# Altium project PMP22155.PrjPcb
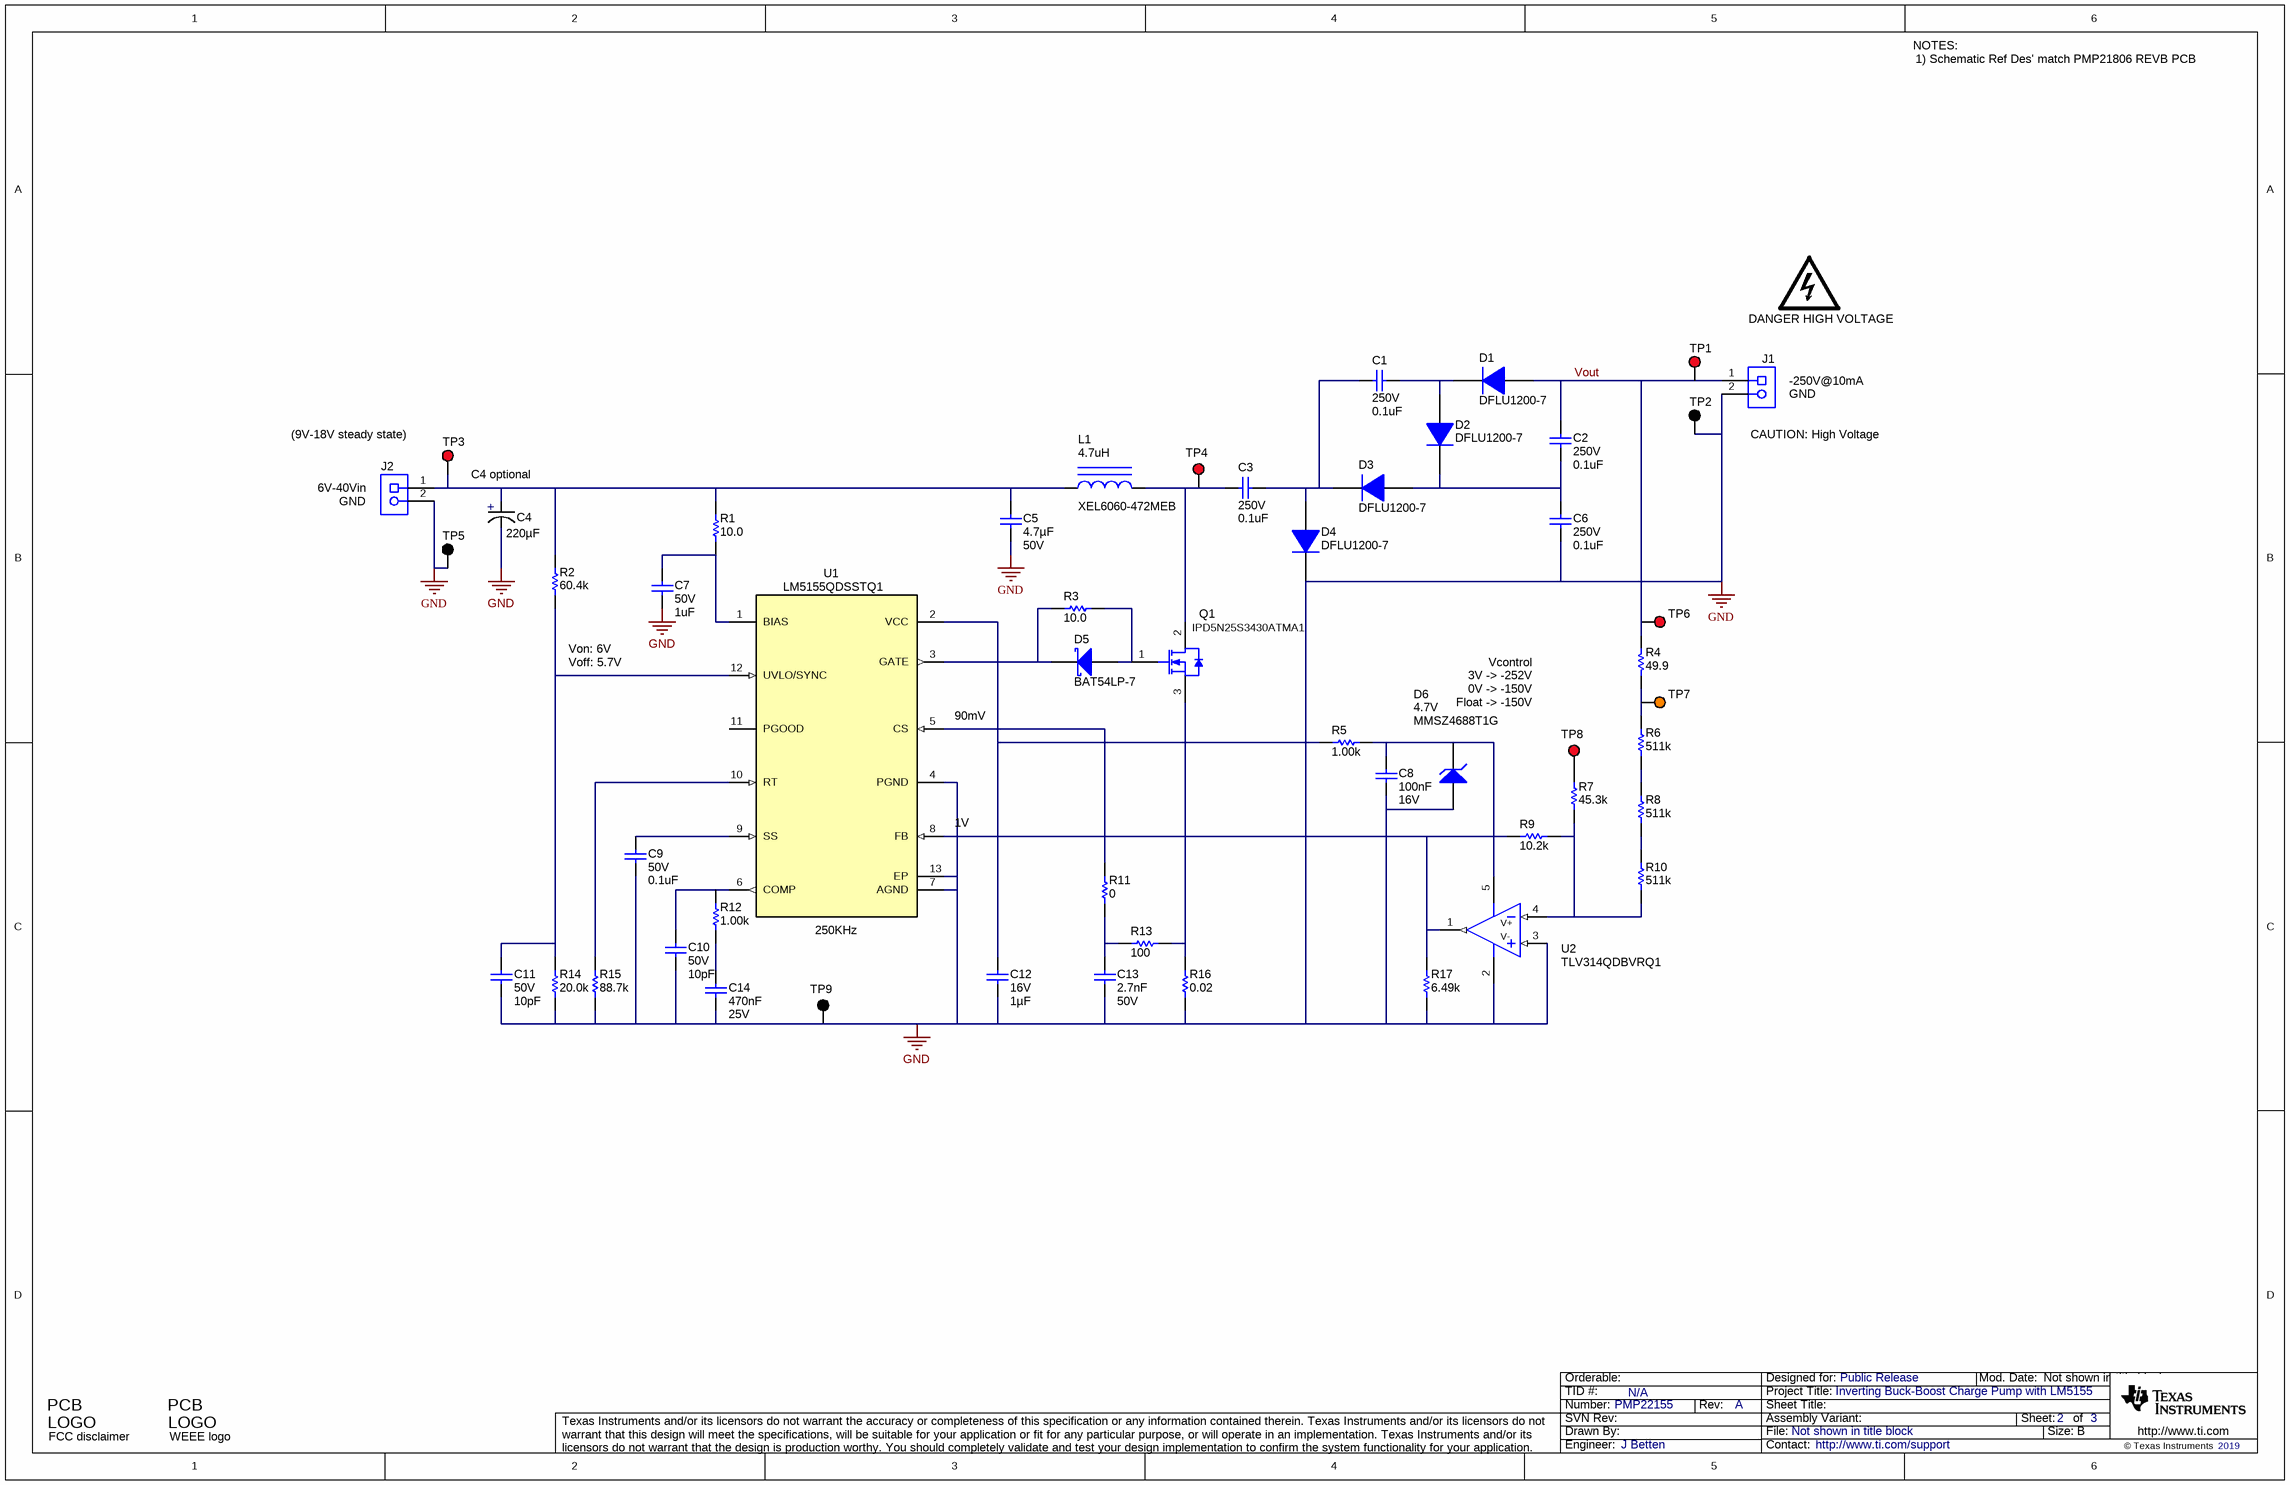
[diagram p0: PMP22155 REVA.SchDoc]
CopyrightYear: 2019; PCB_Layout: J Betten; PCB_Rev: B; PRJ_Customer: Public Release; PRJ_Engineer: J Betten; PRJ_Number: PMP22155; PRJ_Title: Inverting Buck-Boost Charge Pump with LM5155; SCH_Rev: A; TechSupport: http://www.ti.com/support; TID: N/A
1 sheet, 55 parts. Net scope: global (net labels, ports and power ports of the same name join across sheets).
Board file: PMP21806 REVB PCB.PcbDoc

## Sheet PMP22155 REVA.SchDoc
size 431 x 279 mm; Date: Not shown in title block; ApprovedBy: Not shown in title block; CheckedBy: Not shown in title block; Author: Not shown in title block; CompanyName: Not shown in title block; Engineer: Not shown in title block; Organization: Not shown in title block; Address1: Not shown in title block; Address2: Not shown in title block; Address3: Not shown in title block; Address4: Not shown in title block; DocumentNumber: 2; Revision: Use project parameter SCH_Rev; SheetNumber: 2; SheetTotal: 3; PageSetup: Record=PageOptions¦CenterHorizontal=True¦CenterVertical=True¦PrintScale=1.00¦XCorrection=1.00¦YCorrection=1.00¦PrintKind=0¦BorderSize=5000000¦LeftOffset=0¦BottomOffset=0¦Orientation=2¦PaperLength=1000¦PaperWidth=1000¦Scale=100¦PaperSource=15¦PrintQuality=600¦MediaType=1¦DitherType=10¦PaperKind=Letter¦PrintScaleMode=1

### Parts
C1  VDC_V: 250V  ValueDisplayed: 0.1uF  [1210_220]  (hidden comment: GRM32DR72E104KW01L)
C2  VDC_V: 250V  ValueDisplayed: 0.1uF  [1210_220]  (hidden comment: GRM32DR72E104KW01L)
C3  VDC_V: 250V  ValueDisplayed: 0.1uF  [1210_220]  (hidden comment: GRM32DR72E104KW01L)
C4  Cap_F: 220µF  [FP-EEHZS1H221P_RADIAL_SMD-MFG]  (hidden comment: EEHZS1H221P)
C5  ValueDisplayed: 4.7µF  VDC_V: 50V  [1206_190]  (hidden comment: CGA5L3X7R1H475K160AE)
C6  VDC_V: 250V  ValueDisplayed: 0.1uF  [1210_220]  (hidden comment: GRM32DR72E104KW01L)
C7  VDC_V: 50V  ValueDisplayed: 1uF  [0805_HV]  (hidden comment: CGA4J3X7R1H105K125AB)
C8  Cap_F: 100nF  VDC_V: 16V  [0603S]  (hidden comment: CGJ3E2X7R1C104K080AA)
C9  VDC_V: 50V  ValueDisplayed: 0.1uF  [0603L]  (hidden comment: CGA3E2X7R1H104K080AA)
C10  VDC_V: 50V  ValueDisplayed: 10pF  [0603L]  (hidden comment: GRM1885C1H100JA01D)
C11  VDC_V: 50V  ValueDisplayed: 10pF  [0603L]  (hidden comment: GRM1885C1H100JA01D)
C12  VDC_V: 16V  ValueDisplayed: 1µF  [0603L]  (hidden comment: GCM188R71C105KA64J)
C13  Cap_F: 2.7nF  VDC_V: 50V  [0603S]  (hidden comment: GRM188R71H272KA01D)
C14  Cap_F: 470nF  VDC_V: 25V  [0603]  (hidden comment: GCM188R71E474KA64D)
D1  DFLU1200-7  [PowerDI123]
D2  DFLU1200-7  [PowerDI123]
D3  DFLU1200-7  [PowerDI123]
D4  DFLU1200-7  [PowerDI123]
D5  BAT54LP-7  [X1-DFN1006-2]
D6  MMSZ4688T1G  value 4.7V  [SOD-123]
J1  ED555/2DS  [TERM_BLK_ED555-2DS]  (value not drawn)
J2  ED555/2DS  [TERM_BLK_ED555-2DS]  (value not drawn)
L1  XEL6060-472MEB  ValueDisplayed: 4.7uH  [XEL6060]
LOGO1  DANGER HIGH VOLTAGE  [IEC_HighVoltage_Small]  (no BOM)
Logo2  FCC disclaimer  [FCC_disclaimer]  (no BOM)
Logo3  WEEE logo  [WEEE_Minimum]  (no BOM)
Q1  IPD5N25S3430ATMA1  [DPAK]
R1  ValueDisplayed: 10.0  [0603L]  (hidden comment: CRCW060310R0FKEA)
R2  ValueDisplayed: 60.4k  [0603L]  (hidden comment: CRCW060360K4FKEA)
R3  ValueDisplayed: 10.0  [0603L]  (hidden comment: CRCW060310R0FKEA)
R4  value 49.9  [0603L]  (hidden comment: CRCW060349R9FKEA)
R5  ValueDisplayed: 1.00k  [0603S]  (hidden comment: CRCW06031K00FKEA)
R6  ValueDisplayed: 511k  [0603L]  (hidden comment: CRCW0603511KFKEA)
R7  ValueDisplayed: 45.3k  [0603]  (hidden comment: CRCW060345K3FKEA)
R8  ValueDisplayed: 511k  [0603L]  (hidden comment: CRCW0603511KFKEA)
R9  ValueDisplayed: 10.2k  [0603]  (hidden comment: CRCW060310K2FKEA)
R10  ValueDisplayed: 511k  [0603L]  (hidden comment: CRCW0603511KFKEA)
R11  ValueDisplayed: 0  [0603L]  (hidden comment: CRCW06030000Z0EA)
R12  ValueDisplayed: 1.00k  [0603]  (hidden comment: CRCW06031K00FKEA)
R13  ValueDisplayed: 100  [0603L]  (hidden comment: CRCW0603100RFKEA)
R14  ValueDisplayed: 20.0k  [0603L]  (hidden comment: CRCW060320K0FKEA)
R15  ValueDisplayed: 88.7k  [0603L]  (hidden comment: CRCW060388K7FKEA)
R16  ValueDisplayed: 0.02  [1206]  (hidden comment: CSR1206FK20L0)
R17  ValueDisplayed: 6.49k  [0603L]  (hidden comment: CRCW06036K49FKEA)
TP1  5010  [Keystone5010]  (value not drawn)
TP2  5011  [Keystone5011]  (value not drawn)
TP3  5010  [Keystone5010]  (value not drawn)
TP4  5000  [Keystone5000]  (value not drawn)
TP5  5011  [Keystone5011]  (value not drawn)
TP6  5010  [Keystone5010]  (value not drawn)
TP7  5013  [Keystone5013]  (value not drawn)
TP8  5000  [Keystone5000]  (value not drawn)
TP9  5001  [Keystone5001]  (value not drawn)
U1  LM5155QDSSTQ1  [DSS0012C]
U2  TLV314QDBVRQ1  [DBV0005A_N]

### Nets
GND: C4.1(CATHODE) C5.2 C6.2 C7.2 C8.2 C9.2 C10.2 C11.2 C12.1 C13.2 C14.2 D4.1(K) D6.2(A) J1.2 J2.2 R14.1 R15.1 R16.1 R17.1 TP2.1 TP5.1 TP9.1 U1.4(PGND) U1.7(AGND) U1.13(EP) U2.2(V-) U2.3(IN+)
Vout: C2.1 D1.2(A) J1.1 R4.1 TP1.1 TP6.1
NetC1_1: C1.1 C3.2 D3.1(K) D4.2(A)
NetC1_2: C1.2 D1.1(K) D2.2(A)
NetC2_2: C2.2 C6.1 D2.1(K) D3.2(A)
NetC3_1: C3.1 L1.2 Q1.2(D) TP4.1
NetC4_2: C4.2(ANODE) C5.1 J2.1 L1.1 R1.2 R2.2 TP3.1
NetC7_1: C7.1 R1.1 U1.1(BIAS)
NetC8_1: C8.1 D6.1(K) R5.1 U2.5(V+)
NetC9_1: C9.1 U1.9(SS)
NetC10_1: C10.1 R12.2 U1.6(COMP)
NetC11_1: C11.1 R2.1 R14.2 U1.12(UVLO/SYNC)
NetC12_2: C12.2 R5.2 U1.2(VCC)
NetC13_1: C13.1 R11.1 R13.1
NetC14_1: C14.1 R12.1
NetD5_1: D5.1(K) R3.2 U1.3(GATE)
NetD5_2: D5.2(A) Q1.1(G) R3.1
NetQ1_3: Q1.3(S) R13.2 R16.2
NetR4_2: R4.2 R6.2 TP7.1
NetR6_1: R6.1 R8.2
NetR7_1: R7.1 R9.2 R10.1 U2.4(IN-)
NetR7_2: R7.2 TP8.1
NetR8_1: R8.1 R10.2
NetR9_1: R9.1 R17.2 U1.8(FB) U2.1(OUT)
NetR11_2: R11.2 U1.5(CS)
NetR15_2: R15.2 U1.10(RT)

Not connected (* = marked no-connect by the designer): U1 11(PGOOD)

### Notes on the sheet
- NOTES:
- 1) Schematic Ref Des' match PMP21806 REVB PCB
- (9V-18V steady state)
- (near J1) -250V@10mA
- (near J1) GND
- (near J1) CAUTION: High Voltage
- (near J2) 6V-40Vin
- (near J2) GND
- C4 optional
- Von: 6V
- Voff: 5.7V
- Vcontrol
- 3V -> -252V
- 0V -> -150V
- Float -> -150V
- (near U1) 90mV
- 1V
- (near U1) 250KHz

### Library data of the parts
C1-C3 C6 = CMP-0009192-2: CAP, CERM, 0.1 uF, 250 V, +/- 10%, X7R, 1210; Manufacturer: MuRata; TaMin_C: -55°C; Polarized: N; SizeAreaWB_mm2: 14.7; Value1: Unknown; U/M: EA; Value: 0.1uF; TaMax_C: 125°C; SizeZ_mm: 2.2; SizeX_mm: 3.2; SizeY_mm: 2.5; Cap_Case: 1210; SizeArea_mm2: 8; Cap_F: 100nF; AEC Category: Q200
C4 = CMP-0087071-1: 220µF 50V Aluminum Polymer Capacitor Radial, Can - SMD 13 mOhm 4000 Hrs @ 125°C; Manufacturer: Panasonic Electronic Components; SizeZ_mm: 16.8mm; AEC Grade: Grade 1; Symbol Name: SYM-EEHZS1H221P; IRMS_A: 3.7A; Tolerance_%: 20%; AEC Qualified: Yes
C5 = CMP-0085349-1: CAP, CERM, 4.7 µF, 50 V,+/- 10%, X7R, AEC-Q200 Grade 1, 1206; Manufacturer: TDK; Cap_Case: 1206; AEC Category: Q200; SizeY_mm: 1.6; TaMin_C: -55°C; TaMax_C: 125°C; U/M: EA; AEC Qualified: Y; SizeAreaWB_mm2: 10.92; AEC Grade: 1; SizeZ_mm: 1.9; SizeArea_mm2: 5.12; Value: 4.7uF; Polarized: N; SizeX_mm: 3.2
C7 = CMP-0007976-2: CAP, CERM, 1 uF, 50 V, +/- 10%, X7R, AEC-Q200 Grade 1, 0805; Manufacturer: TDK; TaMin_C: -55°C; ESR_ohm: 8.782m; Polarized: N; SizeAreaWB_mm2: 6.75; Value1: 0.008782 ohm; U/M: EA; Value: 1uF; TaMax_C: 125°C; SizeZ_mm: 1.45; SizeX_mm: 2; SizeY_mm: 1.25; Cap_Case: 0805; SizeArea_mm2: 2.5; AEC Qualified: Y; Cap_F: 1µF; IRMS_A: 2.20488A; AEC Grade: 1; AEC Category: Q200
C8 = CMP-0007106-4: CAP, CERM, 0.1 uF, 16 V, +/- 10%, X7R, AEC-Q200 Grade 1, 0603; Manufacturer: TDK; TaMin_C: -55°C; Polarized: N; SizeAreaWB_mm2: 4.68; Value1: Unknown; U/M: EA; Value: 0.1uF; TaMax_C: 125°C; SizeZ_mm: 1; SizeX_mm: 1.6; SizeY_mm: 0.8; Cap_Case: 0603; SizeArea_mm2: 1.28; AEC Qualified: Y; AEC Category: Q200
C9 = CMP-0007078-4: CAP, CERM, 0.1 uF, 50 V, +/- 10%, X7R, AEC-Q200 Grade 1, 0603; Manufacturer: TDK; TaMin_C: -55°C; ESR_ohm: 0.0296; Polarized: N; SizeAreaWB_mm2: 4.68; Value1: 0.0296 ohm; U/M: EA; Value: 0.1uF; TaMax_C: 125°C; SizeZ_mm: 1; SizeX_mm: 1.6; SizeY_mm: 0.8; Cap_Case: 0603; SizeArea_mm2: 1.28; AEC Qualified: Y; Cap_F: 100nF; IRMS_A: 9.7199dA; AEC Category: Q200
C10 C11 = CMP-0007170-4: CAP, CERM, 10 pF, 50 V, +/- 5%, C0G/NP0, 0603; Manufacturer: MuRata; TaMin_C: -55°C; Polarized: N; SizeAreaWB_mm2: 4.68; Value1: Unknown; U/M: EA; Value: 10pF; TaMax_C: 125°C; SizeZ_mm: 1; SizeX_mm: 1.6; SizeY_mm: 0.8; Cap_Case: 0603; SizeArea_mm2: 1.28; AEC Category: Q200
C12 = CMP-0079154-1: CAP, CERM, 1 µF, 16 V,+/- 10%, X7R, AEC-Q200 Grade 1, 0603; Manufacturer: MuRata; SizeAreaWB_mm2: 4.68; SizeArea_mm2: 1.28; AEC Qualified: Y; AEC Category: Q200; Value: 1uF; TaMax_C: 125°C; SizeZ_mm: 1; Polarized: N; TaMin_C: -55°C; SizeY_mm: 0.8; U/M: EA; SizeX_mm: 1.6; Cap_Case: 0603
C13 = CMP-0007447-4: CAP, CERM, 2700 pF, 50 V, +/- 10%, X7R, 0603; Manufacturer: MuRata; TaMin_C: -55°C; Polarized: N; SizeAreaWB_mm2: 4.68; Value1: Unknown; U/M: EA; Value: 2700pF; TaMax_C: 125°C; SizeZ_mm: 1; SizeX_mm: 1.6; SizeY_mm: 0.8; Cap_Case: 0603; SizeArea_mm2: 1.28; AEC Category: Q200
C14 = CMP-0007142-4: CAP, CERM, 0.47 uF, 25 V, +/- 10%, X7R, AEC-Q200 Grade 1, 0603; Manufacturer: MuRata; TaMin_C: -55°C; Polarized: N; SizeAreaWB_mm2: 4.68; Value1: Unknown; U/M: EA; Value: 0.47uF; TaMax_C: 125°C; SizeZ_mm: 1; SizeX_mm: 1.6; SizeY_mm: 0.8; SizeArea_mm2: 1.28; AEC Qualified: Y; AEC Category: Q200
D1-D4 = CMP-0077072-2: Diode, Superfast Rectifier, 200 V, 1 A, AEC-Q101, PowerDI123; Manufacturer: Diodes Inc.; Vf_V: 980mV; Value: 200V; Value1: 1A; Value2: 0.98V; TJmax_C: 150°C; AEC Category: Q101; AEC Qualified: Y; Green_Lifecycle: Not Set; Green_REACh: Incomplete; SizeArea_mm2: 6.586; SizeAreaWB_mm2: 13.066; SizeX_mm: 3.7; SizeY_mm: 1.78; SizeZ_mm: 0.98
D5 = CMP-0076931-2: Diode, Schottky, 30 V, 0.2 A, 1.00x0.50x0.60mm; Manufacturer: Diodes Inc.; Vr_V: 30V; SizeX_mm: 1.0; SizeZ_mm: 0.53; Io_A: 200mA; Value: 30V; Vf_V: 1V; AEC Category: Q101; Green_Lifecycle: Not Set; SizeAreaWB_mm2: 3.2; Value1: 0.2A; Green_REACh: Incomplete; SizeY_mm: 0.6
D6 = CMP-0005785-3: Diode, Zener, 4.7 V, 500 mW, SOD-123; Manufacturer: ON Semiconductor; Value1: 0.5W; RJA_CperW: 340; SizeAreaWB_mm2: 13.095; Power_W: 500mW; SizeX_mm: 3.85; SizeY_mm: 1.7; SizeZ_mm: 1.35; SizeArea_mm2: 6.545; AEC Category: Q101
J1 J2 = CMP-0074913-1: Terminal Block, 3.5mm Pitch, 2x1, TH; Manufacturer: On-Shore Technology; Cert_CULUS: Y; CNHeader: False; ContactFinish: Brass; CT: True; Current_A: 6A; Gender: Female; Green_Lifecycle: Active; Green_REACh: Passed; Pitch_mm: 3.5; Row_Count: 1; Shrouded: N; Voltage_V: 150V
L1 = CMP-0061110-1: Inductor, Shielded, Composite, 4.7 uH, 11.4 A, 0.01502 ohm, AEC-Q200 Grade 1, SMD; Manufacturer: Coilcraft; Isat: 11.4A @ 30% inductance drop; Irms: 12.1A @ 40C rise; SizeAreaWB_mm2: 71.5616; Value: 4.7uH; Imax_A: 11.4A; SizeZ_mm: 6.1; SizeX_mm: 6.36; SizeY_mm: 6.56; SizeArea_mm2: 41.7216; Ind_H: 4.7µH; AEC Qualified: Y; AEC Grade: 1; AEC Category: Q200
LOGO1 = CMP-0074835-1: IEC 61010-1 High Voltage Warning; SymbolCreator: a0412235
Logo2 = CMP-0074847-1: FCC_disclaimer; Library Reference: Logo
Logo3 = CMP-0074769-1
Q1 = CMP-0082696-2: MOSFET, N-CH, 250 V, 5 A, AEC-Q101, DPAK; Manufacturer: Infineon Technologies; Alternate Manufacturer: None; Value2: 4.7 nC; AEC Qualified: Y; SizeX_mm: 9.91; VdsMax_V: 250V; ChType: N; Value: 250V; AEC Category: Q101; SizeY_mm: 6.54; SizeZ_mm: 2.29; Value1: ? ohm; SizeArea_mm2: 64.8114; ChMode: Enhancement; Vgs_V: 20V; QgTyp_nC: 4.7; IdsMax_A: 5A; SizeAreaWB_mm2: 101.7114
R1 R3 = CMP-0022003-4: RES, 10.0, 1%, 0.1 W, AEC-Q200 Grade 0, 0603; Manufacturer: Vishay-Dale; Power_W: 100mW; TempCo: 100 ppm/C; Value_Code: 10R0; Value: 10.0; EIA_Code: E96; Res_ohm: 10; SizeX_mm: 1.6; SizeY_mm: 0.8; SizeZ_mm: 1; Value2: 0.1W; SizeArea_mm2: 1.28; AEC Qualified: Y; VDC_V: 75V; AEC Category: Q200; AEC Grade: 0
R2 = CMP-0022532-4: RES, 60.4 k, 1%, 0.1 W, AEC-Q200 Grade 0, 0603; Manufacturer: Vishay-Dale; Power_W: 100mW; TempCo: 100 ppm/C; Value_Code: 60k4; Value: 60.4k; EIA_Code: E96; SizeX_mm: 1.6; SizeY_mm: 0.8; SizeZ_mm: 1; Value2: 0.1W; SizeArea_mm2: 1.28; AEC Qualified: Y; VDC_V: 75V; AEC Category: Q200; AEC Grade: 0
R4 = CMP-0022448-4: RES, 49.9, 1%, 0.1 W, AEC-Q200 Grade 0, 0603; Manufacturer: Vishay-Dale; Value_Code: 49R9; Power_W: 100mW; Value2: 0.1W; VDC_V: 75V; TempCo: 100 ppm/C; EIA_Code: E96; AEC Category: Q200; AEC Grade: 0; AEC Qualified: Y; SizeArea_mm2: 1.28; SizeX_mm: 1.6; SizeY_mm: 0.8; SizeZ_mm: 1
R5 R12 = CMP-0022109-5: RES, 1.00 k, 1%, 0.1 W, AEC-Q200 Grade 0, 0603; Manufacturer: Vishay-Dale; Power_W: 100mW; TempCo: 100 ppm/C; Value_Code: 1k00; Value: 1.00k; EIA_Code: E96; Res_ohm: 1k; SizeX_mm: 1.6; SizeY_mm: 0.8; SizeZ_mm: 1; Value2: 0.1W; SizeArea_mm2: 1.28; AEC Qualified: Y; VDC_V: 75V; AEC Category: Q200; AEC Grade: 0
R6 R8 R10 = CMP-0022480-4: RES, 511 k, 1%, 0.1 W, AEC-Q200 Grade 0, 0603; Manufacturer: Vishay-Dale; Power_W: 100mW; TempCo: 100 ppm/C; Value: 511k; EIA_Code: E96; SizeX_mm: 1.6; SizeY_mm: 0.8; SizeZ_mm: 1; Value2: 0.1W; SizeArea_mm2: 1.28; AEC Qualified: Y; VDC_V: 75V; AEC Category: Q200; AEC Grade: 0
R7 = CMP-0022430-4: RES, 45.3 k, 1%, 0.1 W, AEC-Q200 Grade 0, 0603; Manufacturer: Vishay-Dale; Power_W: 100mW; TempCo: 100 ppm/C; Value_Code: 45k3; Value: 45.3k; EIA_Code: E96; SizeX_mm: 1.6; SizeY_mm: 0.8; SizeZ_mm: 1; Value2: 0.1W; SizeArea_mm2: 1.28; AEC Qualified: Y; VDC_V: 75V; AEC Category: Q200; AEC Grade: 0
R9 = CMP-0021999-4: RES, 10.2 k, 1%, 0.1 W, AEC-Q200 Grade 0, 0603; Manufacturer: Vishay-Dale; Power_W: 100mW; TempCo: 100 ppm/C; Value_Code: 10k2; Value: 10.2k; EIA_Code: E96; SizeX_mm: 1.6; SizeY_mm: 0.8; SizeZ_mm: 1; Value2: 0.1W; SizeArea_mm2: 1.28; AEC Qualified: Y; VDC_V: 75V; AEC Category: Q200; AEC Grade: 0
R11 = CMP-0025697-4: RES, 0, 5%, 0.1 W, AEC-Q200 Grade 0, 0603; Manufacturer: Vishay-Dale; Power_W: 100mW; TempCo: 200 ppm/C; Value_Code: 0000; Value: 0; EIA_Code: E24; SizeX_mm: 1.6; SizeY_mm: 0.8; SizeZ_mm: 1; Value2: 0.1W; SizeArea_mm2: 1.28; AEC Qualified: Y; VDC_V: 75V; AEC Category: Q200
R13 = CMP-0021991-4: RES, 100, 1%, 0.1 W, AEC-Q200 Grade 0, 0603; Manufacturer: Vishay-Dale; Power_W: 100mW; TempCo: 100 ppm/C; Value_Code: 100R; Value: 100; EIA_Code: E96; SizeX_mm: 1.6; SizeY_mm: 0.8; SizeZ_mm: 1; Value2: 0.1W; SizeArea_mm2: 1.28; AEC Qualified: Y; VDC_V: 75V; AEC Category: Q200; AEC Grade: 0
R14 = CMP-0022204-4: RES, 20.0 k, 1%, 0.1 W, AEC-Q200 Grade 0, 0603; Manufacturer: Vishay-Dale; Power_W: 100mW; TempCo: 100 ppm/C; Value_Code: 20k0; Value: 20.0k; EIA_Code: E96; Res_ohm: 20k; SizeX_mm: 1.6; SizeY_mm: 0.8; SizeZ_mm: 1; Value2: 0.1W; SizeArea_mm2: 1.28; AEC Qualified: Y; VDC_V: 75V; AEC Category: Q200; AEC Grade: 0
R15 = CMP-0022632-4: RES, 88.7 k, 1%, 0.1 W, AEC-Q200 Grade 0, 0603; Manufacturer: Vishay-Dale; Power_W: 100mW; TempCo: 100 ppm/C; Value_Code: 88k7; Value: 88.7k; EIA_Code: E96; SizeX_mm: 1.6; SizeY_mm: 0.8; SizeZ_mm: 1; Value2: 0.1W; SizeArea_mm2: 1.28; AEC Qualified: Y; VDC_V: 75V; AEC Category: Q200; AEC Grade: 0
R16 = CMP-0017260-2: RES, 0.02, 1%, 0.5 W, 1206; Manufacturer: Stackpole Electronics Inc; Power_W: 500mW; TempCo: 100 ppm/C; Value_Code: R020; U/M: EA; Value: 0.02; EIA_Code: E96; SizeX_mm: 3.2; SizeY_mm: 1.6; SizeZ_mm: 1.35; Value2: 0.5W; SizeArea_mm2: 5.12; AEC Category: Q200
R17 = CMP-0022561-4: RES, 6.49 k, 1%, 0.1 W, AEC-Q200 Grade 0, 0603; Manufacturer: Vishay-Dale; Power_W: 100mW; TempCo: 100 ppm/C; Value_Code: 6k49; Value: 6.49k; EIA_Code: E96; SizeX_mm: 1.6; SizeY_mm: 0.8; SizeZ_mm: 1; Value2: 0.1W; SizeArea_mm2: 1.28; AEC Qualified: Y; VDC_V: 75V; AEC Category: Q200; AEC Grade: 0
TP1 TP3 TP6 = CMP-0055147-1: Test Point, Multipurpose, Red, TH; Manufacturer: Keystone; CNHeader: FALSE; Green_Lifecycle: Active; Green_REACh: Passed; ContactFinish: Silver; CT: TRUE
TP2 TP5 = CMP-0055148-1: Test Point, Multipurpose, Black, TH; Manufacturer: Keystone; CNHeader: FALSE; Green_Lifecycle: Active; Green_REACh: Passed; ContactFinish: Silver; CT: TRUE
TP4 TP8 = CMP-0055137-1: Test Point, Miniature, Red, TH; Manufacturer: Keystone; CNHeader: FALSE; ContactFinish: Silver; CT: TRUE; Green_Lifecycle: Active; Green_REACh: Passed
TP7 = CMP-0055150-1: Test Point, Multipurpose, Orange, TH; Manufacturer: Keystone; CNHeader: FALSE; Green_Lifecycle: Active; Green_REACh: Passed; ContactFinish: Silver; CT: TRUE
TP9 = CMP-0055138-1: Test Point, Miniature, Black, TH; Manufacturer: Keystone; CNHeader: FALSE; ContactFinish: Silver; CT: TRUE; Green_Lifecycle: Active; Green_REACh: Passed
U1 = CMP-0081538-1: Automotive Grade 2.2-MHz Wide Input Non-synchronous Boost Controller, DSS0012C (WSON-12); Alternate PartNumber: LM5155QDSSRQ1; Alternate Manufacturer: Texas Instruments; SizeAreaWB_mm2: 12; SizeZ_mm: 0.8; SizeX_mm: 2; SizeY_mm: 3; SizeArea_mm2: 6; CompType: IC; AEC Qualified: Y; AEC Category: Q200
U2 = CMP-0073534-1: 3-MHz, Low-Power, Internal EMI Filter, RRIO, Operational Amplifier, DBV0005A (SOT-23-5); Alternate PartNumber: TLV314QDBVTQ1; Alternate Manufacturer: Texas Instruments; SizeAreaWB_mm2: 14.82; U/M: EA; SizeZ_mm: 1.45; SizeX_mm: 2.8; SizeY_mm: 2.9; SizeArea_mm2: 8.12; CompType: IC

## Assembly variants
001: not fitted C10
